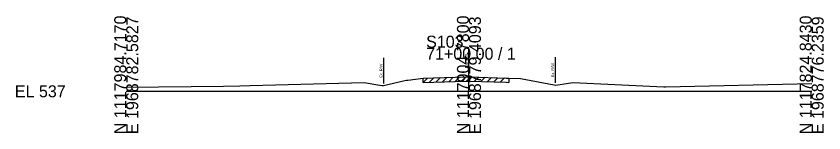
# Model space of a CAD drawing. Extents: x -26 to 163, y -10 to 24018.
# Drawn here: x -25.7 to 162.8, y 18990.3 to 19017.5 of the extents above; entities that cross this region are included whole.
import ezdxf

# ---------------------------------------------------------------- set-up
doc = ezdxf.new("R2010")
doc.units = 0
for name, color, linetype in [('RD_GPK_XS_Cell', 7, 'Continuous'), ('RD_XS_ExGround', 7, 'Continuous'), ('RD_XS_ExPaveRet', 7, 'Continuous'), ('RD_XS_ExRW', 7, 'Continuous'), ('RD_XS_TX_Elev_EX', 7, 'Continuous')]:
    doc.layers.add(name, color=color, linetype=linetype)

msp = doc.modelspace()

# ---------------------------------------------------------------- linework, layer by layer
at = {"layer": 'RD_GPK_XS_Cell'}
for p, q in [((80, 19000), (80, 19010.18)), ((0, 19000), (80, 19000)), ((80, 19000), (160, 19000))]:
    msp.add_line(p, q, dxfattribs=at)
at = {"layer": 'RD_XS_ExGround'}
msp.add_lwpolyline([(0, 19001), (22.71, 19001.22), (26.54, 19001.29), (28.9, 19001.35), (55.55, 19002.09), (59.7, 19001.38), (60.06, 19001.32), (65.04, 19002.5), (65.42, 19002.6), (65.75, 19002.64), (69.29, 19003.06), (79.31, 19003.37), (80.18, 19003.39), (88.69, 19003.1), (89.32, 19003.08), (92.02, 19002.98), (99.92, 19001.49), (100.29, 19001.42), (104.23, 19002.05), (125.47, 19001.05), (125.84, 19001.04), (160, 19001.85)], dxfattribs=at)
at = {"layer": 'RD_XS_ExPaveRet'}
for p, q in [((69.29, 19002.06), (70.32, 19003.1)), ((69.29, 19002.06), (69.29, 19003.06)), ((69.29, 19002.06), (79.31, 19002.37)), ((70.79, 19002.11), (71.82, 19003.14)), ((72.29, 19002.16), (73.32, 19003.19)), ((73.79, 19002.2), (74.82, 19003.23)), ((75.29, 19002.25), (76.32, 19003.28)), ((76.79, 19002.29), (77.82, 19003.32)), ((78.29, 19002.34), (79.32, 19003.37)), ((79.31, 19002.37), (80.18, 19002.39)), ((79.79, 19002.38), (80.78, 19003.37)), ((80.18, 19002.39), (88.69, 19002.1)), ((81.29, 19002.36), (82.26, 19003.32)), ((82.79, 19002.3), (83.76, 19003.27)), ((84.29, 19002.25), (85.26, 19003.22)), ((85.79, 19002.2), (86.76, 19003.17)), ((87.29, 19002.15), (88.26, 19003.12)), ((89.32, 19003.08), (89.32, 19002.08)), ((88.69, 19002.1), (89.32, 19002.08))]:
    msp.add_line(p, q, dxfattribs=at)
at = {"layer": 'RD_XS_ExRW'}
for p, q in [((100.11, 19007.95), (100.11, 19001.95)), ((60.06, 19007.82), (60.06, 19001.82))]:
    msp.add_line(p, q, dxfattribs=at)

# ---------------------------------------------------------------- texts
at = {"layer": 'RD_GPK_XS_Cell'}
for s, p in [('N 1117984.7170', (0, 18990)), ('E 1968782.5827', (2.8, 18990)), ('N 1117904.7800', (80, 18990)), ('E 1968779.4093', (82.8, 18990)), ('N 1117824.8430', (160, 18990)), ('E 1968776.2359', (162.8, 18990))]:
    msp.add_text(s, height=2.8, rotation=90, dxfattribs=at).set_placement(p)
for s, p in [('S103', (70, 19010.18)), ('71+00.00 / 1', (70, 19007.38)), ('EL 537', (-26, 18998.6))]:
    msp.add_text(s, height=2.8, dxfattribs=at).set_placement(p)
at = {"layer": 'RD_XS_ExRW'}
for p in [(59.81, 19003.16), (99.86, 19003.3)]:
    msp.add_text('Ex. R/W ', height=0.65, rotation=90, dxfattribs=at).set_placement(p)
at = {"layer": 'RD_XS_TX_Elev_EX'}
msp.add_text('540.39', height=0.8, rotation=90, dxfattribs=at).set_placement((79.9, 19005.39))

doc.saveas('drawing.dxf')
